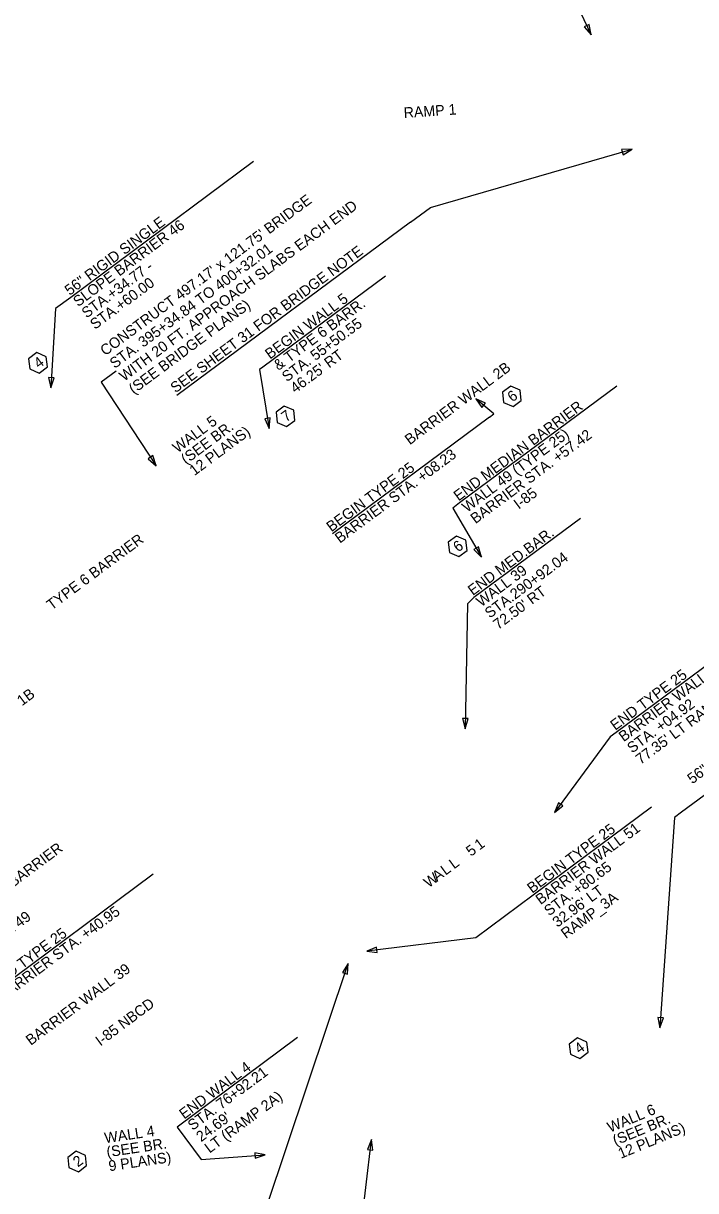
# Model space of a CAD drawing. Extents: x 1609621 to 1611756, y 1093008 to 1094970.
# Drawn here: x 1610636 to 1611016, y 1093621 to 1094282 of the extents above; entities that cross this region are included whole.
import ezdxf

# ---------------------------------------------------------------- set-up
doc = ezdxf.new("R2010")
doc.units = 0
for name, color, linetype in [('RD_PD_GR_TX', 7, 'Continuous'), ('RD_SHT_Misc1', 7, 'Continuous'), ('RD_SHT_TX', 7, 'Continuous'), ('RD_TX_Bridge', 7, 'Continuous'), ('RD_TX_RoadID', 7, 'Continuous')]:
    doc.layers.add(name, color=color, linetype=linetype)

msp = doc.modelspace()

# ---------------------------------------------------------------- linework, layer by layer
at = {"layer": 'RD_PD_GR_TX'}
for points in [[(1610734.06, 1093582.51), (1610773.55, 1093611.86), (1610819.84, 1093749.78)], [(1610823.95, 1093594.01), (1610826.48, 1093595.89), (1610832.88, 1093650.14)]]:
    msp.add_lwpolyline(points, dxfattribs=at)
for points in [[(1610819.47, 1093743.79), (1610819.84, 1093749.78), (1610816.52, 1093744.78)], [(1610833.74, 1093644.2), (1610832.88, 1093650.14), (1610830.66, 1093644.56)]]:
    msp.add_lwpolyline(points, close=True, dxfattribs=at)
at = {"layer": 'RD_SHT_TX'}
for p, q in [((1610766.3, 1094203.48), (1610662.94, 1094126.64)), ((1610840.88, 1094138.69), (1610771.57, 1094087.18)), ((1610971.59, 1094076.37), (1610882.71, 1094010.3)), ((1610899.72, 1094058.89), (1610810.84, 1093992.82)), ((1610950.99, 1094001.59), (1610890.77, 1093956.83)), ((1611060.15, 1093946.6), (1610971.27, 1093880.53)), ((1611156.42, 1093945.56), (1611008.22, 1093835.4)), ((1610991.21, 1093838.14), (1610924.33, 1093788.42)), ((1610709.63, 1093800.28), (1610620.75, 1093734.21)), ((1610791.18, 1093707.86), (1610723.09, 1093657.24))]:
    msp.add_line(p, q, dxfattribs=at)
for points in [[(1610662.94, 1094126.64), (1610654.43, 1094120.32), (1610651.65, 1094075.46)], [(1610771.57, 1094087.18), (1610769.63, 1094085.73), (1610775.08, 1094052.51)], [(1610899.72, 1094058.89), (1610902.13, 1094060.68), (1610891.85, 1094069.22)], [(1610882.71, 1094010.3), (1610878.89, 1094007.46), (1610895.07, 1093979.72)], [(1610890.77, 1093956.83), (1610887.15, 1093953.24), (1610885.85, 1093882.53)], [(1610971.27, 1093880.53), (1610967.86, 1093878), (1610936.44, 1093835.16)], [(1611008.22, 1093835.4), (1611004.18, 1093832.39), (1610995.95, 1093713.36)], [(1610924.33, 1093788.42), (1610891.97, 1093764.37), (1610830.24, 1093756.83)], [(1610723.09, 1093657.24), (1610736.76, 1093638.86), (1610772.81, 1093641.62)]]:
    msp.add_lwpolyline(points, dxfattribs=at)
for points in [[(1610649.13, 1094093.05), (1610643.8, 1094095.36), (1610639.13, 1094091.89), (1610639.8, 1094086.12), (1610645.14, 1094083.81), (1610649.8, 1094087.28)], [(1610650.46, 1094081.34), (1610651.65, 1094075.46), (1610653.56, 1094081.15)], [(1610916.96, 1094074.14), (1610911.63, 1094076.44), (1610906.96, 1094072.97), (1610907.63, 1094067.2), (1610912.97, 1094064.9), (1610917.63, 1094068.37)], [(1610788.98, 1094062.78), (1610783.64, 1094065.08), (1610778.98, 1094061.62), (1610779.65, 1094055.85), (1610784.98, 1094053.54), (1610789.65, 1094057.01)], [(1610897.3, 1094066.71), (1610891.85, 1094069.22), (1610895.32, 1094064.32)], [(1610772.61, 1094057.98), (1610775.08, 1094052.51), (1610775.68, 1094058.48)], [(1610886.27, 1093989.24), (1610880.94, 1093991.54), (1610876.28, 1093988.08), (1610876.95, 1093982.31), (1610882.28, 1093980), (1610886.94, 1093983.47)], [(1610890.81, 1093983.95), (1610895.07, 1093979.72), (1610893.49, 1093985.51)], [(1610884.4, 1093888.35), (1610885.85, 1093882.53), (1610887.51, 1093888.29)], [(1610938.62, 1093840.75), (1610936.44, 1093835.16), (1610941.12, 1093838.91)], [(1610835.81, 1093759.08), (1610830.24, 1093756.83), (1610836.18, 1093755.99)], [(1610994.8, 1093719.24), (1610995.95, 1093713.36), (1610997.9, 1093719.03)], [(1610954.73, 1093705.34), (1610949.4, 1093707.64), (1610944.74, 1093704.18), (1610945.41, 1093698.41), (1610950.74, 1093696.1), (1610955.4, 1093699.57)], [(1610671.28, 1093641.25), (1610665.95, 1093643.55), (1610661.29, 1093640.09), (1610661.96, 1093634.32), (1610667.29, 1093632.01), (1610671.95, 1093635.48)], [(1610767.15, 1093639.62), (1610772.81, 1093641.62), (1610766.92, 1093642.72)]]:
    msp.add_lwpolyline(points, close=True, dxfattribs=at)
at = {"layer": 'RD_TX_Bridge'}
msp.add_line((1610855, 1094169.19), (1610723.01, 1094071.08), dxfattribs=at)
for points in [[(1610946.77, 1094314.58), (1610940.39, 1094310.49), (1610957.08, 1094275.12)], [(1610855, 1094169.19), (1610866.21, 1094177.53), (1610980.23, 1094210.42)], [(1610688.68, 1094084.87), (1610680.23, 1094078.59), (1610711.21, 1094031.38)]]:
    msp.add_lwpolyline(points, dxfattribs=at)
for points in [[(1610953.2, 1094279.7), (1610957.08, 1094275.12), (1610956.01, 1094281.03)], [(1610975.1, 1094207.33), (1610980.23, 1094210.42), (1610974.23, 1094210.31)], [(1610706.73, 1094035.37), (1610711.21, 1094031.38), (1610709.33, 1094037.08)]]:
    msp.add_lwpolyline(points, close=True, dxfattribs=at)

# ---------------------------------------------------------------- texts
at = {"layer": 'RD_SHT_Misc1'}
msp.add_text('SHEET 12-1', height=200, rotation=36.62559, dxfattribs=at).set_placement((1609913.35, 1093948.51))
at = {"layer": 'RD_SHT_TX'}
for s, rotation, p in [('56" RIGID SINGLE', 36.62722, (1610662.35, 1094127.45)), ('SLOPE BARRIER 46', 36.62722, (1610667.12, 1094121.03)), ('STA.+34.77 -', 36.62722, (1610671.89, 1094114.61)), ('STA.+60.00', 36.62722, (1610676.66, 1094108.19)), ('BEGIN WALL 5', 36.62559, (1610775.56, 1094091.39)), ('& TYPE 6 BARR.', 36.62559, (1610780.33, 1094084.97)), ('STA. 55+50.55', 36.62559, (1610785.11, 1094078.55)), ("46.25' RT", 36.62559, (1610789.88, 1094072.13)), ('4', 36.62559, (1610644.85, 1094086.13)), ('BARRIER WALL 2B', 36.62559, (1610854.58, 1094042.92)), ('6', 36.62559, (1610912.57, 1094067.14)), ('END MEDIAN BARRIER', 36.62559, (1610882.15, 1094011.13)), ('WALL 5', 36.62559, (1610723.31, 1094038.31)), ('7', 36.62559, (1610784.7, 1094055.86)), ('(SEE BR. ', 36.62559, (1610728.08, 1094031.88)), ('12 PLANS)', 36.62559, (1610732.85, 1094025.46)), ('WALL 49 (TYPE 25)', 36.62559, (1610886.93, 1094004.71)), ('BARRIER STA. +57.42', 36.62559, (1610891.7, 1093998.29)), ('BARRIER STA. +08.23', 36.62559, (1610815.06, 1093987.23)), ('BEGIN TYPE 25 ', 36.62559, (1610810.28, 1093993.66)), ('TYPE 6 BARRIER', 36.62559, (1610652.15, 1093949.44)), ('END MED.BAR.', 36.62722, (1610890.22, 1093957.66)), ('6', 36.62559, (1610881.88, 1093982.24)), ('STA.290+92.04', 36.62722, (1610899.76, 1093944.82)), ('WALL 39', 36.62722, (1610894.99, 1093951.24)), ("72.50' RT", 36.62722, (1610904.53, 1093938.4)), ('BARRIER WALL 51', 36.62559, (1610975.48, 1093874.94)), ('END TYPE 25 ', 36.62559, (1610970.71, 1093881.36)), ("77.35' LT RAMP_3A", 36.62559, (1610985.03, 1093862.1)), ('STA. +04.92', 36.62559, (1610980.26, 1093868.52)), ('56" RIGID SINGLE', 36.62559, (1611014.25, 1093851.09)), ('BEGIN TYPE 25 ', 36.62559, (1610923.73, 1093789.22)), ('BARRIER WALL 51', 36.62559, (1610928.5, 1093782.8)), ('1', 36.62559, (1610893.95, 1093813.65)), ('TYPE 25 BARRIER', 36.62559, (1610602.81, 1093772.12)), ('5', 36.62559, (1610889.17, 1093810.1)), ('L', 36.62559, (1610879.58, 1093802.97)), ('STA. +80.65', 36.62559, (1610933.28, 1093776.38)), ('W', 36.62559, (1610865.25, 1093792.32)), ('A', 36.62559, (1610870.02, 1093795.87)), ('L', 36.62559, (1610874.8, 1093799.42)), ("32.96' LT", 36.62559, (1610938.05, 1093769.96)), ('RAMP_3A', 36.62559, (1610942.82, 1093763.54)), ('BARRIER STA. +40.95', 36.62559, (1610624.97, 1093728.63)), ('WALL 49', 36.62559, (1610614.56, 1093755.39)), ('END TYPE 25 ', 36.62559, (1610620.19, 1093735.05)), ('BARRIER WALL 39', 36.62559, (1610640.37, 1093703.17)), ('4', 36.62559, (1610950.46, 1093698.42)), ('END WALL 4', 36.62559, (1610727.08, 1093661.45)), ('STA. 76+92.21', 36.62559, (1610731.85, 1093655.03)), ('LT (RAMP 2A)', 36.62559, (1610741.4, 1093642.19)), ('WALL 6', 22.50208, (1610967.75, 1093654.03)), ("24.69' ", 36.62559, (1610736.63, 1093648.61)), ('(SEE BR. ', 22.50208, (1610970.81, 1093646.63)), ('WALL 4', 8.41336, (1610682.45, 1093648.07)), ('12 PLANS)', 22.50208, (1610973.87, 1093639.24)), ('(SEE BR. ', 8.41336, (1610683.62, 1093640.16)), ('9 PLANS)', 8.41336, (1610684.79, 1093632.24)), ('2', 36.62559, (1610667.01, 1093634.33))]:
    msp.add_text(s, height=6, rotation=rotation, dxfattribs=at).set_placement(p)
at = {"layer": 'RD_TX_Bridge'}
for s, p in [("CONSTRUCT 497.17' x 121.75' BRIDGE", (1610682.42, 1094093.3)), ('WITH 20 FT. APPROACH SLABS EACH END', (1610693.16, 1094078.85)), ('STA. 395+34.84 TO 400+32.01', (1610687.79, 1094086.08)), ('SEE SHEET 31 FOR BRIDGE NOTE', (1610722.12, 1094072.28)), ('(SEE BRIDGE PLANS)', (1610698.53, 1094071.63))]:
    msp.add_text(s, height=6, rotation=36.62559, dxfattribs=at).set_placement(p)
at = {"layer": 'RD_TX_RoadID'}
for s, rotation, p in [('RAMP 1', 3.85615, (1610851.33, 1094228.08)), ('I-85', 36.62559, (1610916.11, 1094006.49)), ('RAMP 1B', 36.62559, (1610614.99, 1093880.09)), ('I-85 NBCD', 36.62559, (1610679.72, 1093702.77))]:
    msp.add_text(s, height=6, rotation=rotation, dxfattribs=at).set_placement(p)

doc.saveas('drawing.dxf')
